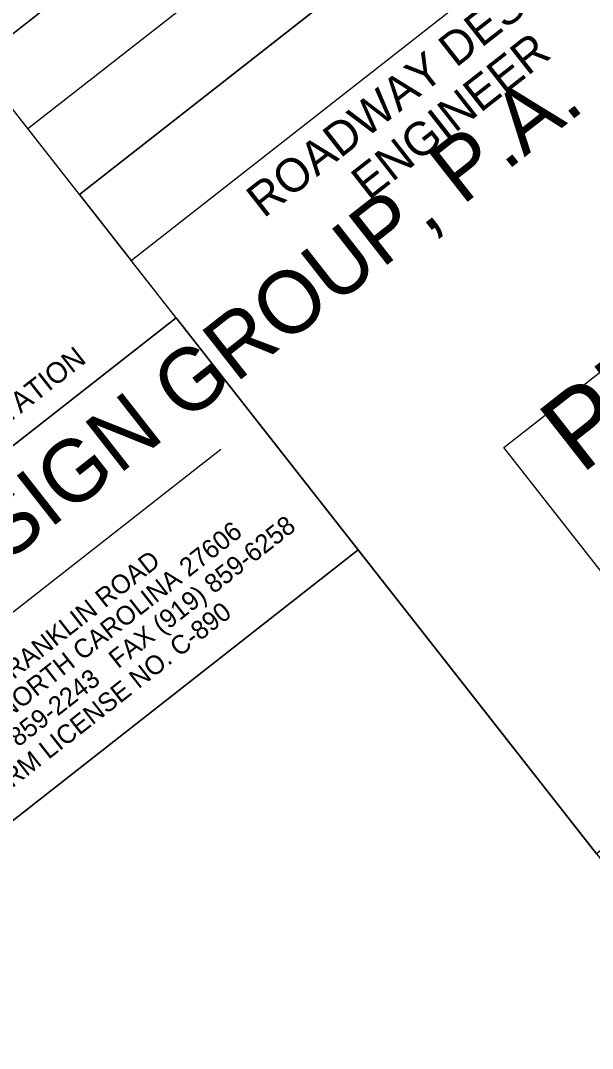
# Model space of a CAD drawing. Extents: x 2176242 to 2178501, y 76147 to 78096.
# Drawn here: x 2177418.9 to 2177504.2, y 77750.4 to 77903.8 of the extents above; entities that cross this region are included whole.
import ezdxf

# ---------------------------------------------------------------- set-up
doc = ezdxf.new("R2010")
doc.units = 0
for name, color, linetype in [('CTL Primary Horizontal and Vertical CELL', 7, 'Continuous'), ('Exist Other Culture Sign Cogo Point CELL', 7, 'Continuous'), ('Exist Property Iron Pin Cogo Elevation', 7, 'Continuous'), ('Exist Structure Minor Storm Sewer Manhole CELL', 7, 'Continuous')]:
    doc.layers.add(name, color=color, linetype=linetype)

msp = doc.modelspace()

# ---------------------------------------------------------------- linework, layer by layer
at = {"layer": 'CTL Primary Horizontal and Vertical CELL'}
msp.add_lwpolyline([(2176602.37, 76823.57), (2177301.95, 77811.08), (2177301.95, 77811.08), (2177306.48, 77814.63), (2177363.51, 77741.87), (2177469.29, 77824.79), (2177519.32, 77760.95), (2177676.76, 77884.36), (2178217.46, 77194.57), (2177036.91, 76269.2)], close=True, dxfattribs=at)
at = {"layer": 'Exist Other Culture Sign Cogo Point CELL'}
for p, q in [((2177420, 77887.66), (2177577.45, 78011.08)), ((2177427.71, 77877.83), (2177585.16, 78001.24)), ((2177427.71, 77877.83), (2177585.16, 78001.24)), ((2177427.71, 77877.83), (2177435.42, 77867.99)), ((2177395.68, 77798.2), (2177448.8, 77839.85))]:
    msp.add_line(p, q, dxfattribs=at)
for points in [[(2177569.7, 78020.95), (2176389.16, 77095.58), (2177036.91, 76269.2), (2178217.46, 77194.57)], [(2177412.26, 77897.54), (2177569.7, 78020.95), (2177585.16, 78001.24), (2177427.71, 77877.83)], [(2177435.42, 77867.99), (2177514.17, 77929.71), (2177583.57, 77841.17), (2177504.83, 77779.45)], [(2177336.36, 77776.51), (2177442.13, 77859.43), (2177469.29, 77824.79), (2177363.51, 77741.87)]]:
    msp.add_lwpolyline(points, close=True, dxfattribs=at)
for start, end in [(38.0911, 218.0911), (218.0911, 38.0911)]:
    msp.add_arc((2177429.08, 77805.47), 0.138, start, end, dxfattribs=at)
at = {"layer": 'Exist Property Iron Pin Cogo Elevation'}
msp.add_lwpolyline([(2177505.52, 77821.6), (2177491.02, 77840.1), (2177606.71, 77930.78), (2177621.21, 77912.29)], close=True, dxfattribs=at)
at = {"layer": 'Exist Structure Minor Storm Sewer Manhole CELL'}
for q in [(2177412.26, 77897.54), (2177336.36, 77776.51)]:
    msp.add_line((2177442.13, 77859.43), q, dxfattribs=at)

# ---------------------------------------------------------------- texts
at = {"layer": 'Exist Other Culture Sign Cogo Point CELL'}
for s, height, rotation, p in [('ROADWAY DESIGN', 5.0001, 38.091, (2177455.19, 77874.21)), ('ENGINEER', 5, 38.091, (2177470.83, 77876.87)), ('SUNGATE DESIGN GROUP, P.A.', 9.3194, 38.0911, (2177352.91, 77772.73)), ('TEL (919) 859-2243   FAX (919) 859-6258', 2.8007, 38.0911, (2177404.63, 77784.38)), ('RALEIGH, NORTH CAROLINA 27606', 2.8007, 38.0911, (2177402.23, 77787.9)), ('905 JONES FRANKLIN ROAD', 2.8007, 38.0911, (2177399.69, 77791.14)), ('ENG FIRM LICENSE NO. C-890', 2.8007, 38.0911, (2177407.86, 77781.52))]:
    msp.add_text(s, height=height, rotation=rotation, dxfattribs=at).set_placement(p)
at = {"layer": 'Exist Property Iron Pin Cogo Elevation'}
msp.add_text('PRELIMINARY PLANS', height=11.52, rotation=38.091, dxfattribs=at).set_placement((2177502.52, 77835.96))
at = {"layer": 'Exist Structure Minor Storm Sewer Manhole CELL'}
msp.add_text('FOR NORTH CAROLINA DEPT. OF TRANSPORTATION', height=3.1013, rotation=38.091, dxfattribs=at).set_placement((2177344.95, 77787.09))

doc.saveas('drawing.dxf')
